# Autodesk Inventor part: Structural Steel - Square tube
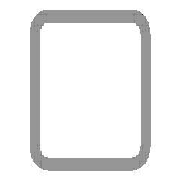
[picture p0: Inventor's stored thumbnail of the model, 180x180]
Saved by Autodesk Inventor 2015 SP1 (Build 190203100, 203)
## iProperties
IsCustomPart: 1
Created: 2011-06
Part Number: Structural Steel - Square tube
Material: Stainless Steel
Document SubType Name: Modeling
Standard: ISO
Designer: Guilherme Augusto Franco de Souza
Standard Revision: Second edition 2001-09-01
Standards Organization: ISO
Language: en-US
Size Designation: 25x25x2
Categories: <MemberInstance><Categories><Category DisplayName="Structural Shapes" InternalName="089c4875-fa83-4c05-b084-43b9cc11f5ed" Mnemonic="GRDR"><CategoryParameter Dis
Stock Number: 25x25x2
Density: 8.08 g/cm^3
Description: ISO 4019 - 25x25x2
Appearance: Steel
G_L: 390,000 mm
G_W: 25,000 mm
G_H: 25,000 mm
+3F952AE1-E171-4758-B047-084C1F7F7CE4+CUTDETAIL1: Miter 45,00 deg
+B56EE3C7-5F2D-4B34-8060-3F06F4014C4C+CUTDETAIL2: Miter 45,00 deg
Author: Guilherme Augusto Franco de Souza
_CCFamilyMember: 2
_CCFamilyDisplayName: ISO 4019 (Square) - Structural steels - Cold-formed, welded, structural hollow sections
_FrameMemberDoc: Frame Member File
_Version: 15.0.0
_GetPNFromCC: 1
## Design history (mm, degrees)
node "Start plane"
node "End plane"
sketch "Sketch"
  geometry: L1 (-12.5, -8.5)-(-12.5, 8.5); L2 (-8.5, 12.5)-(8.5, 12.5); L3 (12.5, 8.5)-(12.5, -8.5); L4 (8.5, -12.5)-(-8.5, -12.5); L5 (-8.5, 10.5)-(8.5, 10.5); L6 (10.5, 8.5)-(10.5, -8.5); L7 (8.5, -10.5)-(-8.5, -10.5); L8 (-10.5, -8.5)-(-10.5, 8.5); L9 (0, 18.66)-(0, -18.66) reference; L10 (-18.66, 0)-(18.66, 0) reference; A1 r 4 centre (-8.5, -8.5) between (-12.5, -8.5) and (-8.5, -12.5); A2 r 4 centre (8.5, 8.5) between (12.5, 8.5) and (8.5, 12.5); A3 r 4 centre (-8.5, 8.5) between (-8.5, 12.5) and (-12.5, 8.5); A4 r 4 centre (8.5, -8.5) between (8.5, -12.5) and (12.5, -8.5); A5 r 2 centre (-8.5, 8.5) between (-8.5, 10.5) and (-10.5, 8.5); A6 r 2 centre (8.5, 8.5) between (10.5, 8.5) and (8.5, 10.5); A7 r 2 centre (8.5, -8.5) between (8.5, -10.5) and (10.5, -8.5); A8 r 2 centre (-8.5, -8.5) between (-10.5, -8.5) and (-8.5, -10.5)
  constraints: 16 end point, 16 point on circle, 8 centre point, 8 tangent, 4 parallel, 3 equal radius, 2 perpendicular, 7 other
  dimensions: "d7" = 4 radius of A1 (= G_IR); "d9" = 25 distance between parallel lines of L1 L3 (= G_W); "d11" = 25 distance between parallel lines of L2 L4 (= G_H); "d12" = 2 distance between parallel lines of L3 L6 (= G_T); "d15" = 12.5 distance between parallel lines of L9 L3 (= 0.5 x d9); "d16" = 12.5 distance between parallel lines of L2 L10 (= 0.5 x d11)
extrude "Body" new body sketch "Sketch" stored distance "d3" = 390 (= G_L); taper "d4" = 0 deg
node "Driven Length"
  sketch "Sketch3"
    geometry: L1 (0, 0)-(10, 0) reference
    constraints: 2 end point, 1 horizontal
  workplane "Work Plane3"
  sketch "Sketch4"
    geometry: L1 (-2, 0.141)-(12, 0.141) reference; L2 (-2, 389.859)-(12, 389.859) reference
    dimensions: "d18" = 389.71716 distance between parallel lines of L1 L2 (derived)
workplane "Work Plane4"
split "Split1"
workplane "Work Plane5"
split "Split2"
body "Solid1"
other parameters: "G_W" = 25 [user parameter; used in 1 equation term], "G_H" = 25 [user parameter; used in 1 equation term], "G_T" = 2 [user parameter; used in 1 equation term], "G_IR" = 4 [user parameter; used in 1 equation term], "G_L" = 390 [user parameter; used in 1 equation term], "G_OFFSET_START" = -0.14142 [user parameter; used in 1 equation term], "G_OFFSET_END" = -0.14142 [user parameter; used in 1 equation term], "d13" = 0.14142 (= -G_OFFSET_START), "d14" = 389.85858 (= G_OFFSET_END + B_L), "d17" = 90 deg, "MAS" = 0.136 [user parameter]
